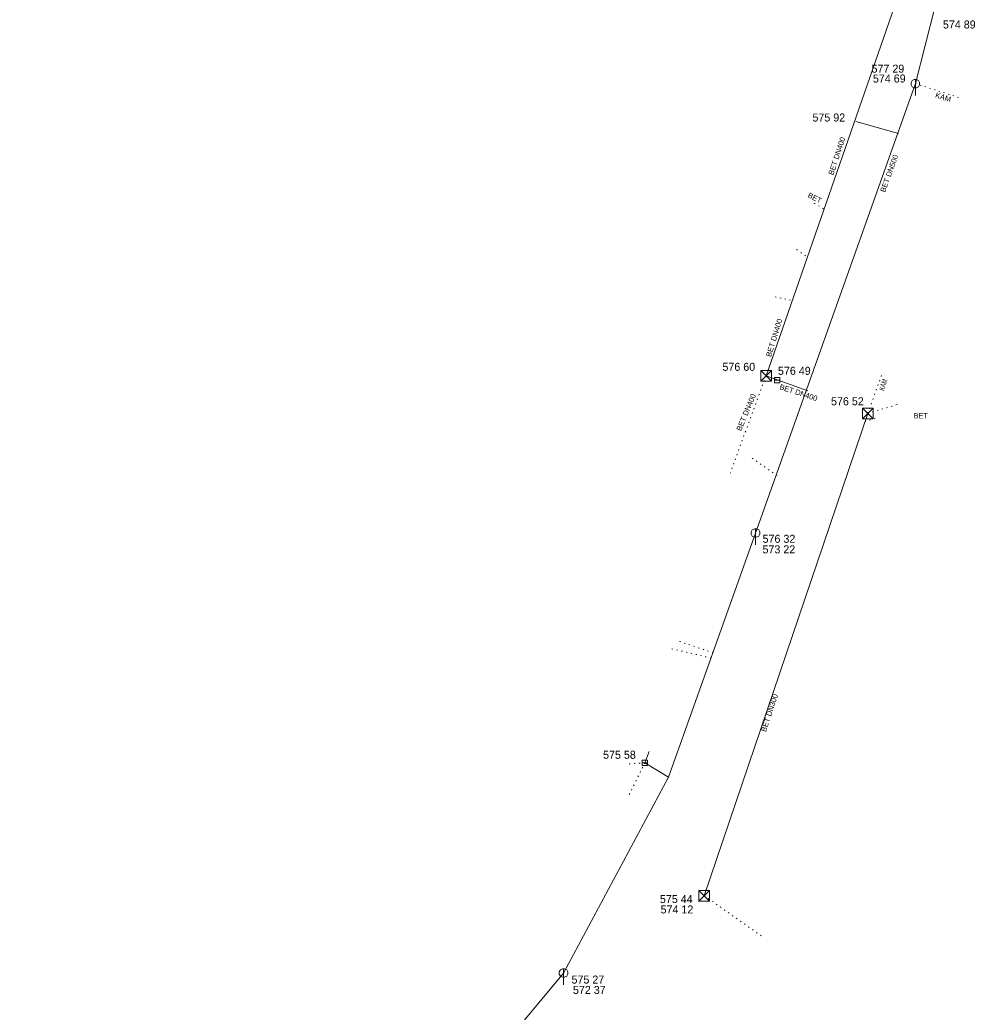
# Model space of a CAD drawing. Extents: x -710806 to -710046, y -1116920 to -1116046.
# Drawn here: x -710171.4 to -710081.9, y -1116258.1 to -1116165.1 of the extents above; entities that cross this region are included whole.
import ezdxf
from ezdxf.enums import TextEntityAlignment as Align

# ---------------------------------------------------------------- set-up
doc = ezdxf.new("R2010")
doc.units = 0
doc.header["$LTSCALE"] = 0.3
doc.linetypes.add('DOTTED', pattern=[1.5, 0.3, -1.2])
for name, color, linetype, lineweight in [('40', 7, 'Continuous', 13), ('41', 7, 'Continuous', 13), ('45', 7, 'DOTTED', 13)]:
    doc.layers.add(name, color=color, linetype=linetype, lineweight=lineweight)
doc.layers.add('43', color=7, linetype='Continuous')
doc.layers.add('44', color=7, linetype='Continuous')

msp = doc.modelspace()

# ---------------------------------------------------------------- linework, layer by layer
at = {"layer": '40', "linetype": 'DOTTED'}
for p, q in [((-710101.52, -1116198.471), (-710104.886, -1116207.607)), ((-710107.317, -1116247.203), (-710101.909, -1116251.008))]:
    msp.add_line(p, q, dxfattribs=at)
at = {"layer": '40'}
msp.add_line((-710107.317, -1116247.203), (-710091.99, -1116201.991), dxfattribs=at)
for points in [[(-710097.606, -1116199.871), (-710101.52, -1116198.471), (-710089.481, -1116163.872), (-710089.946, -1116156.41), (-710097.496, -1116122.299), (-710124.534, -1116116.307)], [(-710171.446, -1116284.268), (-710145.874, -1116273.486), (-710131.257, -1116265.793), (-710127.793, -1116263.212), (-710120.495, -1116254.452), (-710110.653, -1116236.079), (-710102.507, -1116213.21), (-710087.53, -1116171.086), (-710085.71, -1116163.96)]]:
    msp.add_lwpolyline(points, dxfattribs=at)
at = {"layer": '41'}
for p, q in [((-710087.53, -1116170.686), (-710087.53, -1116172.186)), ((-710102.02, -1116197.971), (-710101.02, -1116198.971)), ((-710101.02, -1116197.971), (-710102.02, -1116198.971)), ((-710100.227, -1116198.641), (-710100.727, -1116198.641)), ((-710100.727, -1116198.641), (-710100.727, -1116199.141)), ((-710100.227, -1116198.891), (-710100.727, -1116198.891)), ((-710100.227, -1116199.141), (-710100.227, -1116198.641)), ((-710100.727, -1116199.141), (-710100.227, -1116199.141)), ((-710092.49, -1116201.491), (-710091.49, -1116202.491)), ((-710091.49, -1116201.491), (-710092.49, -1116202.491)), ((-710102.507, -1116212.81), (-710102.507, -1116214.31)), ((-710112.621, -1116234.49), (-710113.121, -1116234.49)), ((-710113.121, -1116234.49), (-710113.121, -1116234.99)), ((-710112.621, -1116234.74), (-710113.121, -1116234.74)), ((-710113.121, -1116234.99), (-710112.621, -1116234.99)), ((-710112.621, -1116234.99), (-710112.621, -1116234.49)), ((-710107.817, -1116246.703), (-710106.817, -1116247.703)), ((-710106.817, -1116246.703), (-710107.817, -1116247.703)), ((-710120.495, -1116254.052), (-710120.495, -1116255.552))]:
    msp.add_line(p, q, dxfattribs=at)
for points in [[(-710087.93, -1116171.186), (-710087.93, -1116170.986), (-710087.83, -1116170.786), (-710087.63, -1116170.686), (-710087.43, -1116170.686), (-710087.23, -1116170.786), (-710087.13, -1116170.986), (-710087.13, -1116171.186), (-710087.23, -1116171.386), (-710087.43, -1116171.486), (-710087.63, -1116171.486), (-710087.83, -1116171.386)], [(-710102.02, -1116197.971), (-710101.02, -1116197.971), (-710101.02, -1116198.971), (-710102.02, -1116198.971)], [(-710092.49, -1116201.491), (-710091.49, -1116201.491), (-710091.49, -1116202.491), (-710092.49, -1116202.491)], [(-710102.907, -1116213.31), (-710102.907, -1116213.11), (-710102.807, -1116212.91), (-710102.607, -1116212.81), (-710102.407, -1116212.81), (-710102.207, -1116212.91), (-710102.107, -1116213.11), (-710102.107, -1116213.31), (-710102.207, -1116213.51), (-710102.407, -1116213.61), (-710102.607, -1116213.61), (-710102.807, -1116213.51)], [(-710107.817, -1116246.703), (-710106.817, -1116246.703), (-710106.817, -1116247.703), (-710107.817, -1116247.703)], [(-710120.895, -1116254.552), (-710120.895, -1116254.352), (-710120.795, -1116254.152), (-710120.595, -1116254.052), (-710120.395, -1116254.052), (-710120.195, -1116254.152), (-710120.095, -1116254.352), (-710120.095, -1116254.552), (-710120.195, -1116254.752), (-710120.395, -1116254.852), (-710120.595, -1116254.852), (-710120.795, -1116254.752)]]:
    msp.add_lwpolyline(points, close=True, dxfattribs=at)
at = {"layer": '45'}
for p, q in [((-710087.53, -1116171.086), (-710083.249, -1116172.463)), ((-710096.133, -1116182.816), (-710097.173, -1116182.2)), ((-710097.817, -1116187.233), (-710098.92, -1116186.464)), ((-710099.219, -1116191.378), (-710100.949, -1116191.011)), ((-710091.99, -1116201.991), (-710090.699, -1116198.41)), ((-710091.99, -1116201.991), (-710089.183, -1116201.159)), ((-710092.271, -1116202.764), (-710091.059, -1116202.417)), ((-710100.477, -1116207.83), (-710102.927, -1116206.117)), ((-710106.672, -1116224.928), (-710110.504, -1116224.021)), ((-710106.473, -1116224.439), (-710109.751, -1116223.324)), ((-710112.871, -1116234.74), (-710114.592, -1116234.866)), ((-710112.871, -1116234.74), (-710114.387, -1116237.803))]:
    msp.add_line(p, q, dxfattribs=at)
at = {"layer": '45', "linetype": 'Continuous'}
msp.add_line((-710093.108, -1116174.649), (-710089.106, -1116175.766), dxfattribs=at)
msp.add_lwpolyline([(-710110.653, -1116236.079), (-710112.871, -1116234.74), (-710112.479, -1116233.689)], dxfattribs=at)

# ---------------------------------------------------------------- texts
at = {"layer": '43'}
for s, p in [('574 89', (-710084.946, -1116165.919)), ('574 69', (-710091.509, -1116170.984)), ('573 22', (-710101.853, -1116215.114)), ('574 12', (-710111.407, -1116248.865)), ('572 37', (-710119.616, -1116256.411))]:
    msp.add_text(s, height=0.75, dxfattribs=at).set_placement(p)
for s, p in [('577 29 ', (-710089.9622, -1116170.059)), ('575 92 ', (-710095.5002, -1116174.638)), ('576 60 ', (-710103.9342, -1116198.006)), ('576 49 ', (-710098.7312, -1116198.38)), ('576 52 ', (-710093.7582, -1116201.235)), ('576 32 ', (-710100.1742, -1116214.125)), ('575 58 ', (-710115.1192, -1116234.369)), ('575 44 ', (-710109.7932, -1116247.894)), ('575 27 ', (-710118.0762, -1116255.44))]:
    msp.add_text(s, height=0.75, dxfattribs=at).set_placement(p, align=Align.CENTER)
at = {"layer": '44'}
for s, rotation, p in [('KAM', 342, (-710085.706, -1116172.364)), ('BET DN400', 72, (-710095.215, -1116179.702)), ('BET DN500', 70.2, (-710090.368, -1116181.317)), ('BET', 333, (-710097.669, -1116181.71)), ('BET DN400', 72.9, (-710101.063, -1116196.737)), ('BET DN400', 342, (-710100.305, -1116199.718)), ('BET DN400', 67.5, (-710103.859, -1116203.688)), ('BET DN300', 72, (-710101.532, -1116231.891))]:
    msp.add_text(s, height=0.5, rotation=rotation, dxfattribs=at).set_placement(p)
at = {"layer": '44', "width": 0.6}
msp.add_text('KAM', height=0.5, rotation=72, dxfattribs=at).set_placement((-710090.463, -1116199.911))
at = {"layer": '44'}
msp.add_text('BET', height=0.5, dxfattribs=at).set_placement((-710087.693, -1116202.469))

doc.saveas('drawing.dxf')
